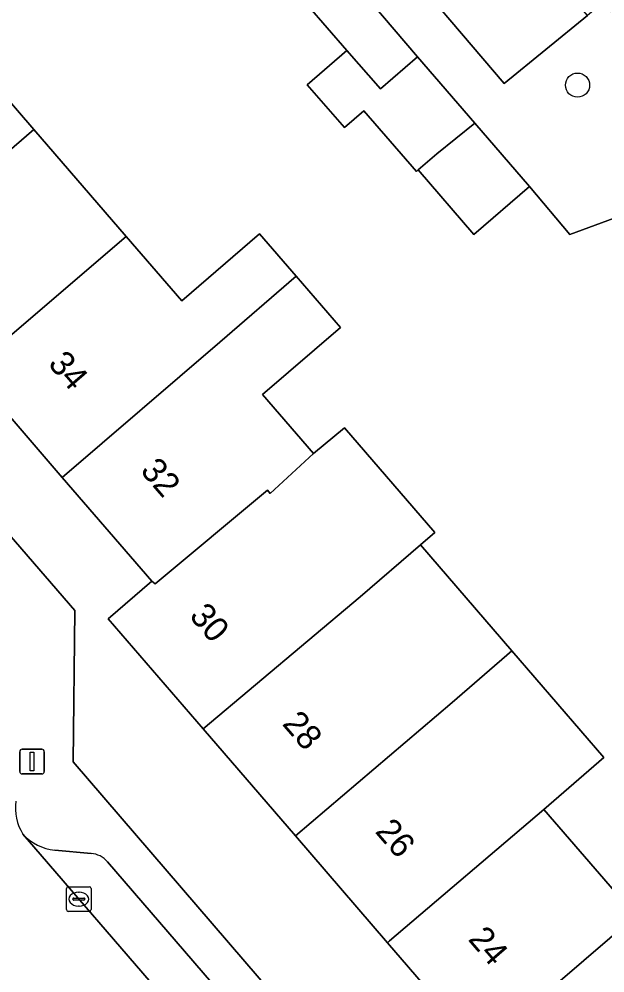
# Model space of a CAD drawing. Extents: x 160304 to 160955, y 383684 to 384161.
# Drawn here: x 160461.92 to 160485.58, y 384055.67 to 384094.2 of the extents above; entities that cross this region are included whole.
import ezdxf

# ---------------------------------------------------------------- set-up
doc = ezdxf.new("R2010")
doc.units = 0
for name, color, linetype in [('IMGEO_Boom', 7, 'Continuous'), ('IMGEO_Erf', 7, 'Continuous'), ('IMGEO_Kolk', 7, 'Continuous'), ('IMGEO_Lichtmast', 7, 'Continuous'), ('IMGEO_Pand', 7, 'Continuous'), ('IMGEO_Pand_nummerreeks', 7, 'Continuous'), ('IMGEO_Parkeervlak_open', 7, 'Continuous'), ('IMGEO_Rijbaan_lokaal_open', 7, 'Continuous'), ('IMGEO_Voetpad_open', 7, 'Continuous')]:
    doc.layers.add(name, color=color, linetype=linetype)

msp = doc.modelspace()

# ---------------------------------------------------------------- linework, layer by layer
at = {"layer": 'IMGEO_Boom'}
msp.add_circle((160484.478, 384091.529), 0.489, dxfattribs=at)
at = {"layer": 'IMGEO_Erf'}
for points in [[(160480.535, 384052.567), (160476.806, 384056.888), (160473.083, 384061.203), (160469.356, 384065.523), (160465.516, 384069.973), (160467.284, 384071.499), (160463.67, 384075.687), (160459.939, 384080.012), (160456.229, 384084.312), (160452.508, 384088.624), (160448.645, 384093.101), (160454.74, 384098.361), (160454.335, 384098.831), (160457.615, 384101.658), (160457.542, 384101.745), (160445.759, 384091.611), (160464.179, 384070.303), (160464.114, 384064.194), (160482.27, 384043.068)], [(160458.201, 384094.743), (160458.796, 384094.053), (160462.523, 384089.733), (160466.243, 384085.421), (160468.493, 384082.814), (160471.638, 384085.527), (160473.112, 384083.818), (160474.901, 384081.745), (160471.757, 384079.032), (160473.809, 384076.654), (160475.061, 384077.691), (160478.712, 384073.459), (160478.133, 384072.959), (160481.824, 384068.681), (160485.546, 384064.367), (160483.121, 384062.275), (160486.83, 384057.977)], [(160487.338, 384086.673), (160484.162, 384085.491), (160482.537, 384087.433), (160480.29, 384085.494), (160478.041, 384088.101), (160477.976, 384088.045), (160475.842, 384090.487), (160475.071, 384089.813), (160473.565, 384091.535), (160475.165, 384092.934), (160473.566, 384094.763)]]:
    msp.add_lwpolyline(points, dxfattribs=at)
at = {"layer": 'IMGEO_Kolk'}
for p, q in [((160463.91, 384059.152), (160464.762, 384059.152)), ((160463.835, 384058.226), (160463.835, 384059.078)), ((160464.323, 384058.932), (160464.348, 384058.932)), ((160464.836, 384059.078), (160464.836, 384058.226)), ((160464.094, 384058.646), (160464.094, 384058.658)), ((160464.532, 384058.609), (160464.134, 384058.609)), ((160464.137, 384058.695), (160464.535, 384058.695)), ((160464.346, 384058.372), (160464.321, 384058.372)), ((160464.578, 384058.658), (160464.578, 384058.646)), ((160464.762, 384058.152), (160463.91, 384058.152))]:
    msp.add_line(p, q, dxfattribs=at)
for points in [[(160463.91, 384059.152), (160464.762, 384059.152)], [(160463.835, 384058.226), (160463.835, 384059.078)], [(160464.836, 384059.078), (160464.836, 384058.226)], [(160464.762, 384058.152), (160463.91, 384058.152)]]:
    msp.add_lwpolyline(points, dxfattribs=at)
for centre, radius, start, end in [((160463.912, 384059.076), 0.0765, 91.552, 178.448), ((160463.912, 384059.076), 0.0765, 91.552, 178.448), ((160464.76, 384059.076), 0.0765, 1.552, 88.448), ((160464.76, 384059.076), 0.0765, 1.552, 88.448), ((160464.134, 384058.655), 0.0403, 85.8775, 175.7526), ((160464.131, 384058.645), 0.0366, 178.938, 274.7102), ((160464.535, 384058.652), 0.043, 264.8664, 352.4533), ((160464.539, 384058.657), 0.0386, 1.7309, 96.639), ((160463.912, 384058.228), 0.0765, 181.552, 268.448), ((160463.912, 384058.228), 0.0765, 181.552, 268.448), ((160464.76, 384058.228), 0.0765, 271.552, 358.448), ((160464.76, 384058.228), 0.0765, 271.552, 358.448)]:
    msp.add_arc(centre, radius, start, end, dxfattribs=at)
for centre, major_axis, ratio, start_param, end_param in [((160464.322, 384058.652), (-0.387, 0.002), 0.722429, 4.712389, 7.853982), ((160464.347, 384058.652), (-0.39, 0.002), 0.717154, 1.570796, 4.712389)]:
    msp.add_ellipse(centre, major_axis=major_axis, ratio=ratio, start_param=start_param, end_param=end_param, dxfattribs=at)
at = {"layer": 'IMGEO_Lichtmast'}
for p, q in [((160461.951, 384063.805), (160461.951, 384064.605)), ((160461.951, 384064.605), (160461.951, 384063.805)), ((160462.051, 384064.705), (160462.841, 384064.705)), ((160462.841, 384064.705), (160462.051, 384064.705)), ((160462.941, 384064.605), (160462.941, 384063.805)), ((160462.941, 384063.805), (160462.941, 384064.605)), ((160462.841, 384063.705), (160462.051, 384063.705)), ((160462.051, 384063.705), (160462.841, 384063.705))]:
    msp.add_line(p, q, dxfattribs=at)
msp.add_lwpolyline([(160462.371, 384064.58), (160462.521, 384064.58), (160462.521, 384063.83), (160462.371, 384063.83), (160462.371, 384064.58)], dxfattribs=at)
for centre, start, end in [((160462.051, 384064.605), 90, 180), ((160462.051, 384064.605), 90, 180), ((160462.841, 384064.605), 0, 90), ((160462.841, 384064.605), 360, 90), ((160462.051, 384063.805), 180, 270), ((160462.051, 384063.805), 180, 270), ((160462.841, 384063.805), 270, 0), ((160462.841, 384063.805), 270, 0)]:
    msp.add_arc(centre, 0.1, start, end, dxfattribs=at)
at = {"layer": 'IMGEO_Pand'}
for points in [[(160475.101, 384096.087), (160473.566, 384094.763), (160475.165, 384092.934), (160476.524, 384091.38), (160478.019, 384092.67)], [(160458.796, 384094.053), (160452.508, 384088.624), (160456.229, 384084.312), (160462.523, 384089.733)], [(160478.019, 384092.67), (160476.524, 384091.38), (160475.165, 384092.934), (160473.565, 384091.535), (160475.071, 384089.813), (160475.842, 384090.487), (160477.976, 384088.045), (160478.041, 384088.101), (160478.793, 384088.749), (160480.327, 384089.995)], [(160478.793, 384088.749), (160478.041, 384088.101), (160480.29, 384085.494), (160482.537, 384087.433), (160480.327, 384089.995)], [(160466.243, 384085.421), (160462.523, 384089.733), (160456.229, 384084.312), (160459.939, 384080.012)], [(160466.243, 384085.421), (160459.939, 384080.012), (160463.67, 384075.687), (160470.03, 384081.15), (160473.112, 384083.818), (160471.638, 384085.527), (160468.493, 384082.814)], [(160467.284, 384071.499), (160467.42, 384071.39), (160471.95, 384075.17), (160472.06, 384075.04), (160473.809, 384076.654), (160471.757, 384079.032), (160474.901, 384081.745), (160473.112, 384083.818), (160470.03, 384081.15), (160463.67, 384075.687)], [(160478.133, 384072.959), (160478.712, 384073.459), (160475.061, 384077.691), (160473.809, 384076.654), (160472.06, 384075.04), (160471.95, 384075.17), (160467.42, 384071.39), (160467.284, 384071.499), (160465.516, 384069.973), (160469.356, 384065.523), (160475.7, 384070.86)], [(160478.133, 384072.959), (160475.7, 384070.86), (160469.356, 384065.523), (160473.083, 384061.203), (160479.42, 384066.59), (160481.824, 384068.681)], [(160476.806, 384056.888), (160476.89, 384056.96), (160483.121, 384062.275), (160485.546, 384064.367), (160481.824, 384068.681), (160479.42, 384066.59), (160473.083, 384061.203)], [(160476.806, 384056.888), (160480.535, 384052.567), (160486.83, 384057.977), (160483.121, 384062.275), (160476.89, 384056.96)], [(160492.216, 384056.496), (160489.185, 384060.009), (160486.83, 384057.977), (160480.535, 384052.567), (160486.663, 384045.465), (160486.77, 384045.457), (160490.75, 384053.58)]]:
    msp.add_lwpolyline(points, close=True, dxfattribs=at)
at = {"layer": 'IMGEO_Parkeervlak_open'}
for points in [[(160474.017, 384104.492), (160471.962, 384102.809), (160481.519, 384091.597), (160484.876, 384094.347), (160474.228, 384106.839)], [(160462.073, 384061.277), (160462.515, 384060.763), (160477.506, 384043.391)], [(160464.829, 384060.5), (160463.369, 384060.633)], [(160477.007, 384046.807), (160465.495, 384060.157)]]:
    msp.add_lwpolyline(points, dxfattribs=at)
for centre, radius, start, end in [((160463.554, 384062.63), 2.006, 222.4313, 264.7219), ((160464.735, 384059.5), 1.004, 40.8562, 84.6455)]:
    msp.add_arc(centre, radius, start, end, dxfattribs=at)
at = {"layer": 'IMGEO_Rijbaan_lokaal_open'}
msp.add_lwpolyline([(160479.834, 384040.678), (160479.686, 384040.851), (160477.506, 384043.391), (160462.515, 384060.763), (160462.073, 384061.277)], dxfattribs=at)
msp.add_arc((160463.828, 384062.342), 2.053, 172.7108, 211.2365, dxfattribs=at)
at = {"layer": 'IMGEO_Voetpad_open'}
for points in [[(160480.83, 384110.285), (160487.225, 384109.82), (160487.26, 384110.289), (160491.194, 384110.005), (160491.157, 384109.534), (160495.602, 384109.211), (160495.282, 384104.793), (160495.752, 384104.76), (160495.48, 384101), (160495.01, 384101.033), (160494.662, 384096.218), (160490.217, 384096.541), (160489.177, 384096.183), (160489.339, 384095.711), (160487.609, 384095.115), (160485.784, 384094.486), (160485.622, 384094.958), (160484.876, 384094.347), (160481.519, 384091.597), (160471.962, 384102.809), (160474.017, 384104.492)], [(160465.206, 384108.28), (160464.817, 384108.006), (160469.146, 384102.989), (160472.884, 384098.657), (160475.101, 384096.087), (160478.019, 384092.67), (160480.327, 384089.995), (160482.537, 384087.433), (160484.162, 384085.491), (160487.338, 384086.673)], [(160477.506, 384043.391), (160479.686, 384040.851), (160482.27, 384043.068), (160464.114, 384064.194), (160464.179, 384070.303), (160445.759, 384091.611)], [(160463.369, 384060.633), (160464.829, 384060.5)], [(160465.495, 384060.157), (160477.007, 384046.807)]]:
    msp.add_lwpolyline(points, dxfattribs=at)
for centre, radius, start, end in [((160463.828, 384062.342), 2.053, 172.7108, 211.2365), ((160463.554, 384062.63), 2.006, 222.4313, 264.7219), ((160464.735, 384059.5), 1.004, 40.8562, 84.6455)]:
    msp.add_arc(centre, radius, start, end, dxfattribs=at)

# ---------------------------------------------------------------- texts
at = {"layer": 'IMGEO_Pand_nummerreeks'}
for s, rotation, p in [('34', 310.7888, (160463.06, 384080.251)), ('32', 310.7888, (160466.786, 384075.933)), ('30', 310.7896, (160468.763, 384070.067)), ('28', 310.7896, (160472.518, 384065.715)), ('26', 310.7896, (160476.27, 384061.366)), ('24', 310.7896, (160480.025, 384057.014))]:
    msp.add_text(s, height=1, rotation=rotation, dxfattribs=at).set_placement(p)

doc.saveas('drawing.dxf')
